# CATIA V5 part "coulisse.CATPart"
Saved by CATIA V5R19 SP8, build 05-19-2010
Part number: coulisse
Publications: "Droite.1", "Droite.2"
Bounding box of the stored display mesh (mm): x -20 to 20, y -10 to 150, z 0 to 0
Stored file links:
  C:\Users\rcousturie\Desktop\EU_thinkMotion\iao\IAO_MMS_Groupe1\flamrini\Lamrini_projet_IAO2011\Lamrini_projet_IAO2011\projet_iao_traindatterrissage\projet_iao_traindatterrissage\coulisse.CATPart
  C:\Users\rcousturie\Desktop\EU_thinkMotion\iao\IAO_MMS_Groupe1\flamrini\Lamrini_projet_IAO2011\Lamrini_projet_IAO2011\projet_iao_traindatterrissage\projet_iao_traindatterrissage\squelettetrain.CATProduct
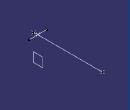
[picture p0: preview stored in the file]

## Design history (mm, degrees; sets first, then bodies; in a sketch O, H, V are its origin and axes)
Set1
  Point1 "Pointb": linked copy from another document
  Plane1: linked copy from another document
  Point2: linked copy from another document
  Point3: linked copy from another document
Set2
  Line1: type PtDir, RefPoint Point1, Direction Plane1, Start -20, End 20
  Line2: type PtPt, LineFirstUpto Point3, FirstPoint Point1, SecondPoint Point2
Body1 (main body)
